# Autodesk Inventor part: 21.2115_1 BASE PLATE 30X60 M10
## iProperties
Created: 2012-10
Part Number: 21.2115_1 BASE PLATE 30X60 M10
Document SubType Name: Modeling
Designer: Administrator
Density: 2.71 g/cm^3
Material: Aluminum-6061
Mass: 63.4152 g
Surface Area: 69.0711 cm^2
Volume: 23.4004 cm^3
Description: BASE PLATE 30X60 M10
Stock Number: 21.2112 CONNECTING PLATE 30X60
Translation Standard: STEP AP214IS
FileName: 21_2113_0_1.stp
PreProcessor: ACIS
PostProcessor: Build: 236a, Release: 2009 RTM - Date: Fri 02/22/2008
Sent Units: MM
Uncertainty: 1e-06
Author: Administrator
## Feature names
1. Base1
2. Hole1
